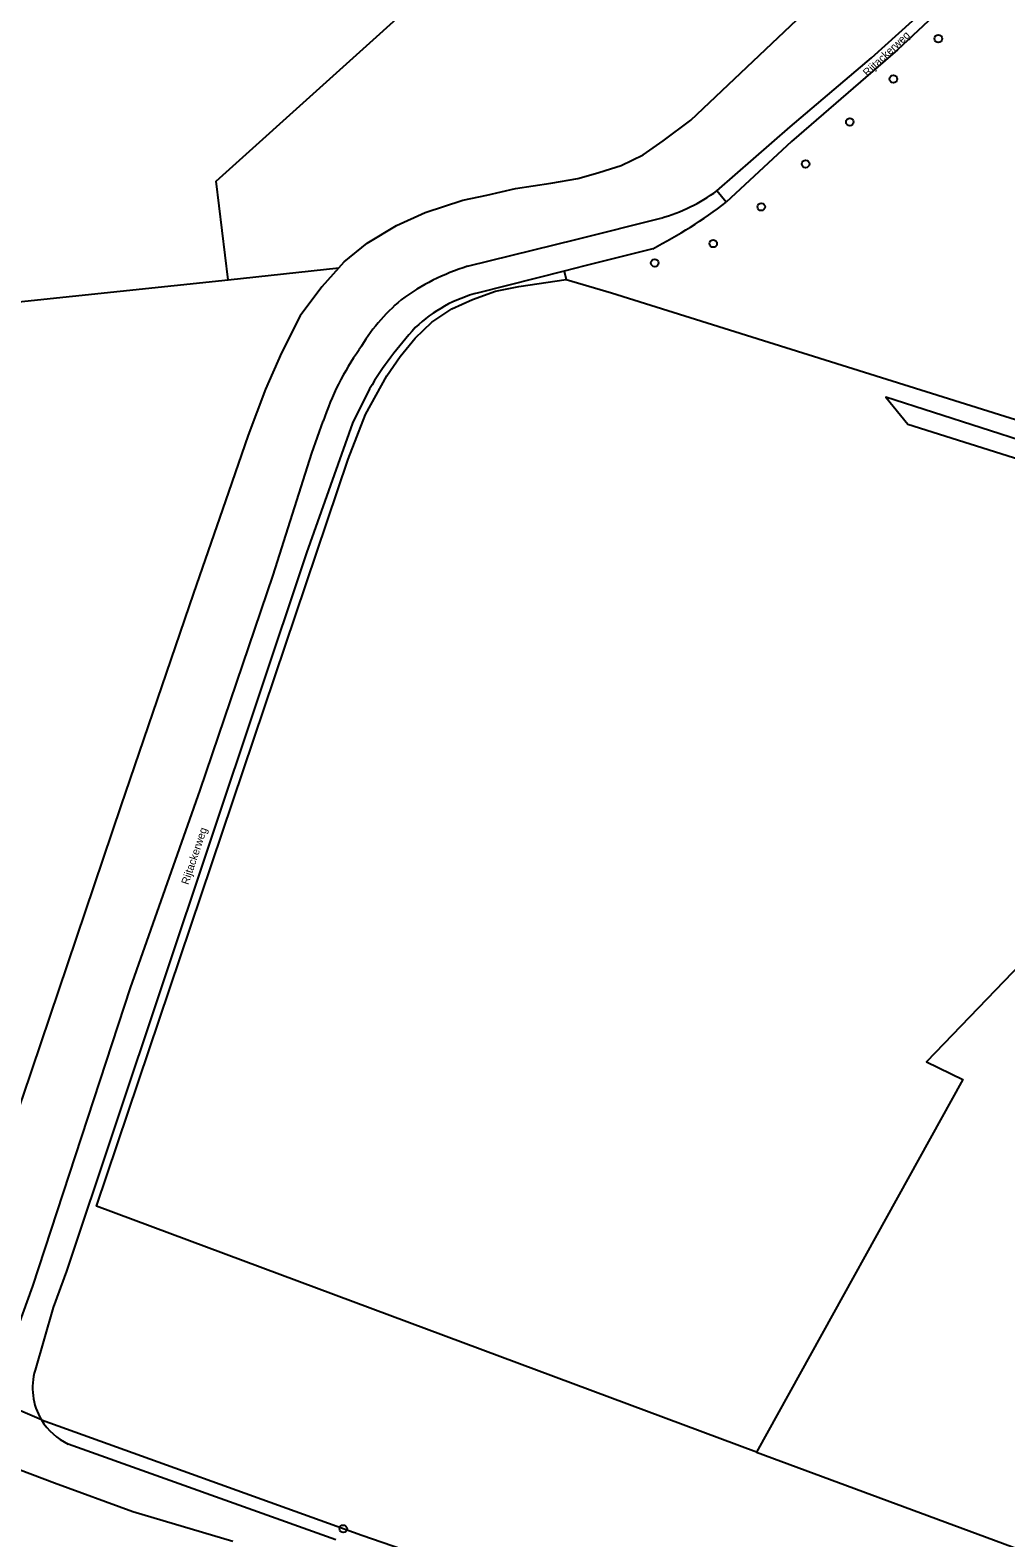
# Model space of a CAD drawing. Extents: x 156061 to 157804, y 383451 to 385640.
# Drawn here: x 156564.9 to 156690.3, y 385074 to 385268.1 of the extents above; entities that cross this region are included whole.
import ezdxf

# ---------------------------------------------------------------- set-up
doc = ezdxf.new("R2010")
doc.units = 0
for name, color, linetype in [('IMGEO_Boom', 7, 'Continuous'), ('IMGEO_Grasland_overig', 7, 'Continuous'), ('IMGEO_Groenvoorziening', 7, 'Continuous'), ('IMGEO_Hek', 7, 'Continuous'), ('IMGEO_Loofbos', 7, 'Continuous'), ('IMGEO_Openbare_ruimte_label', 7, 'Continuous'), ('IMGEO_Rijbaan_lokaal_gesloten', 7, 'Continuous')]:
    doc.layers.add(name, color=color, linetype=linetype)

msp = doc.modelspace()

# ---------------------------------------------------------------- linework, layer by layer
at = {"layer": 'IMGEO_Boom'}
for centre in [(156681.63, 385266.96), (156675.85, 385261.77), (156670.25, 385256.25), (156664.57, 385250.84), (156658.86, 385245.32), (156652.68, 385240.6), (156645.16, 385238.1), (156605.11, 385075.21)]:
    msp.add_circle(centre, 0.489, dxfattribs=at)
at = {"layer": 'IMGEO_Grasland_overig'}
for points in [[(156653.17, 385247.39), (156662.59, 385255.62), (156673.02, 385264.48), (156681.84, 385272.49), (156689.08, 385279.85)], [(156690.23, 385278.51), (156676.4, 385265.53), (156662.75, 385253.71), (156654.37, 385245.91)]]:
    msp.add_lwpolyline(points, dxfattribs=at)
at = {"layer": 'IMGEO_Groenvoorziening'}
for points in [[(156604.54, 385237.46), (156602.37, 385235.01), (156599.58, 385231.31), (156597.17, 385226.55), (156595.13, 385221.87), (156592.88, 385215.94), (156590.35, 385208.6), (156585.87, 385195.59), (156576.52, 385168.23), (156563.92, 385130.88), (156553.4, 385101.35)], [(156633.51, 385237.04), (156633.77, 385235.98)], [(156397.01, 385215.36), (156407.76, 385215.44), (156417.02, 385216.5), (156444.32, 385219.59), (156487.42, 385224.63), (156500, 385226.03), (156522.58, 385228.54), (156556.36, 385232.36), (156590.31, 385235.94)], [(156658.24, 385085.09), (156573.38, 385116.71), (156605.74, 385212.86), (156607.97, 385218.58), (156610.73, 385223.59), (156612.43, 385226.05), (156614.37, 385228.41), (156616.52, 385230.47), (156619.08, 385232.21), (156621.74, 385233.41), (156624.7, 385234.46), (156627.7, 385235.07), (156633.77, 385235.98)], [(156633.77, 385235.98), (156639.59, 385234.27), (156743.63, 385201.6)], [(156738.12, 385201.48), (156729.14, 385204.34), (156699.42, 385212.94), (156674.88, 385220.82), (156677.73, 385217.34), (156702.56, 385209.49), (156714.76, 385205.86), (156727, 385202.73), (156737.58, 385199.28), (156738.12, 385201.48)], [(156743.63, 385201.6), (156729.5, 385186.7), (156715.5, 385172.11), (156680.12, 385135.3), (156684.8, 385133.04), (156658.24, 385085.09)], [(156566.3, 385089.23), (156607.49, 385074.38), (156629.79, 385066.73)], [(156658.24, 385085.09), (156712.13, 385065.11), (156712.19, 385065.09), (156712.02, 385064.64), (156712.96, 385064.3), (156713.14, 385064.81), (156713.45, 385064.69)]]:
    msp.add_lwpolyline(points, dxfattribs=at)
at = {"layer": 'IMGEO_Hek'}
for points in [[(156658.24, 385085.09), (156573.38, 385116.71), (156605.74, 385212.86), (156607.97, 385218.58), (156610.73, 385223.59), (156612.43, 385226.05), (156614.37, 385228.41), (156616.52, 385230.47), (156619.08, 385232.21), (156621.74, 385233.41), (156624.7, 385234.46), (156627.7, 385235.07), (156633.77, 385235.98)], [(156633.77, 385235.98), (156639.59, 385234.27), (156743.63, 385201.6)], [(156715.5, 385172.11), (156680.12, 385135.3), (156684.8, 385133.04), (156658.24, 385085.09)], [(156658.24, 385085.09), (156712.13, 385065.11), (156712.19, 385065.09)]]:
    msp.add_lwpolyline(points, dxfattribs=at)
at = {"layer": 'IMGEO_Loofbos'}
for points in [[(156590.31, 385235.94), (156588.75, 385248.63), (156660.98, 385313.75)], [(156604.54, 385237.46), (156605.24, 385238.26), (156608.17, 385240.65), (156611.94, 385242.92), (156615.64, 385244.58), (156620.47, 385246.16), (156623.57, 385246.84), (156627.26, 385247.67), (156631.79, 385248.35), (156635.26, 385248.96), (156637.83, 385249.71), (156638.78, 385250), (156640.85, 385250.62), (156643.68, 385252.02), (156646.25, 385253.83), (156649.8, 385256.48), (156663.45, 385269.37), (156682.46, 385287.84)], [(156590.31, 385235.94), (156604.54, 385237.46)]]:
    msp.add_lwpolyline(points, dxfattribs=at)
at = {"layer": 'IMGEO_Rijbaan_lokaal_gesloten'}
for points in [[(156654.37, 385245.91), (156653.17, 385247.39)], [(156621.1, 385237.67), (156635.18, 385241.18), (156645.97, 385243.88)], [(156644.9, 385239.92), (156636.18, 385237.72), (156633.51, 385237.04)], [(156633.51, 385237.04), (156622.49, 385234.27)], [(156608.5, 385221.91), (156606.3, 385217.49), (156600.39, 385200.8), (156569.52, 385108.36), (156567.83, 385103.67), (156565.49, 385095.64)], [(156562.24, 385098.26), (156565.2, 385106.42), (156577.76, 385144.83), (156586.71, 385170.27), (156596.08, 385197.94), (156601.08, 385213.63), (156602.54, 385217.74)], [(156324.12, 385168.82), (156326.22, 385167.86), (156431.78, 385130.12), (156500, 385105.74), (156557.53, 385085.07), (156567.97, 385081.12), (156578.06, 385077.45), (156590.93, 385073.63)], [(156566.3, 385089.23), (156559.95, 385091.94)], [(156604.14, 385073.81), (156569.75, 385086.11)]]:
    msp.add_lwpolyline(points, dxfattribs=at)
for centre, radius, start, end in [((156639.93, 385265.4), 22.36, 285.687, 306.3099), ((156613.48, 385300.07), 67.86, 297.587, 307.0549), ((156629.54, 385210.3), 28.64, 107.1308, 126.3635), ((156628.71, 385214.35), 24.95, 130.3617, 149.6838), ((156627.03, 385216.49), 18.35, 104.3064, 133.588), ((156649.42, 385197.49), 47.65, 137.3421, 149.1702), ((156634.61, 385207.37), 33.7, 144.4964, 162.0851), ((156573.15, 385093.35), 7.99, 163.3523, 211.0386), ((156573.14, 385093.34), 7.98, 211.0034, 244.8903)]:
    msp.add_arc(centre, radius, start, end, dxfattribs=at)

# ---------------------------------------------------------------- texts
at = {"layer": 'IMGEO_Openbare_ruimte_label'}
for rotation, p in [(43.419, (156672.51, 385262.04)), (71.5107, (156585.2, 385158.01))]:
    msp.add_text('Rijtackerweg', height=1, rotation=rotation, dxfattribs=at).set_placement(p)

doc.saveas('drawing.dxf')
